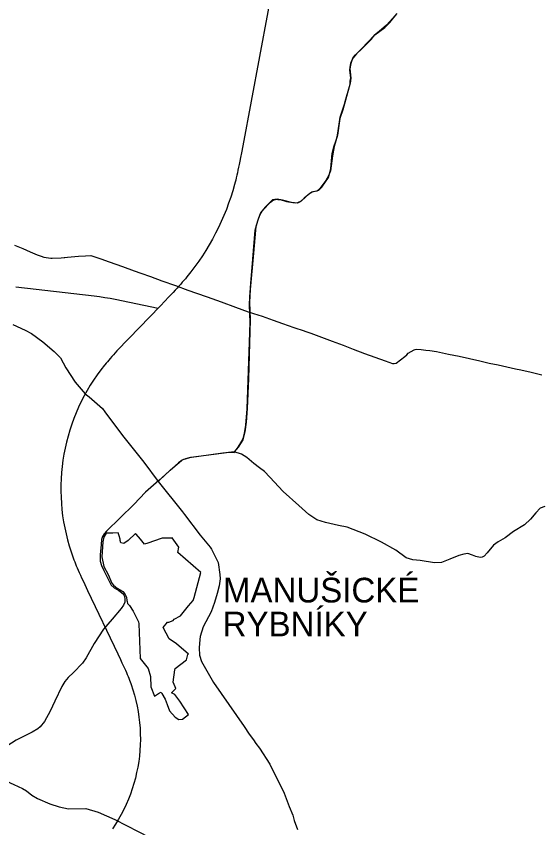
# Model space of a CAD drawing. Extents: x -789162 to -606354, y -1062736 to -945481.
# Drawn here: x -727625 to -725497, y -975863 to -972579 of the extents above; entities that cross this region are included whole.
import ezdxf

# ---------------------------------------------------------------- set-up
doc = ezdxf.new("R2010")
doc.units = 0
for name, color, linetype in [('_SIRSI VZTAHY_CYKLOTRASY MISTNI S', 7, 'Continuous'), ('_SIRSI VZTAHY_NATURA_EVL', 7, 'Continuous'), ('_SIRSI VZTAHY_NATURA_EVL_POPIS_KOD', 7, 'Continuous'), ('_SIRSI VZTAHY_SILNICE I TRIDY_NAVRH', 7, 'Continuous'), ('_SIRSI VZTAHY_SILNICE III TRIDY_STAV', 7, 'Continuous'), ('_SIRSI VZTAHY_VTL PLYNOVOD', 7, 'Continuous')]:
    doc.layers.add(name, color=color, linetype=linetype)

msp = doc.modelspace()

# ---------------------------------------------------------------- linework, layer by layer
at = {"layer": '_SIRSI VZTAHY_CYKLOTRASY MISTNI S'}
for points in [[(-727050.7, -974462), (-727044.1, -974456.3), (-727001.4, -974416), (-726991.4, -974406.6), (-726955.1, -974376.9), (-726945.6, -974371.9), (-726939.4, -974369.8), (-726917.6, -974363.2), (-726762.7, -974343.4), (-726742.3, -974343.9), (-726725.9, -974322.6), (-726711.9, -974299.1), (-726704.6, -974283.7), (-726700.1, -974266.1), (-726694.7, -974233.5), (-726690.3, -974167.8), (-726680, -973898.4), (-726678.4, -973818.6), (-726680.3, -973747.8), (-726679.3, -973714.4), (-726673.9, -973643.2), (-726666.5, -973562.6), (-726657.3, -973444.5), (-726646.5, -973407.4), (-726638.2, -973384.2), (-726627.7, -973365.1), (-726595.9, -973332), (-726590.3, -973327.8), (-726580.4, -973322.1), (-726570.4, -973319.8), (-726565.4, -973320.3), (-726556.6, -973321.1), (-726530.5, -973328.6), (-726505.5, -973333.1), (-726492.5, -973334.3), (-726484.5, -973332.6), (-726469.9, -973325.5), (-726436.3, -973295.2), (-726428, -973289.7), (-726407.4, -973285.6), (-726400.1, -973283), (-726394, -973277.6), (-726388, -973270.4), (-726373.1, -973249.1), (-726360.3, -973231), (-726352.1, -973202.4), (-726350.6, -973194.9), (-726345.2, -973134.6), (-726338.7, -973107.2), (-726329.3, -973080), (-726325.6, -973066.9), (-726322.6, -973051.6), (-726313.5, -972987.2), (-726296, -972934.5), (-726293.1, -972924.1), (-726273.4, -972854), (-726272.6, -972841.7), (-726270.4, -972828.1), (-726273.9, -972796.7), (-726273.4, -972785.2), (-726270.9, -972768.7), (-726260.4, -972746.3), (-726251, -972734.8), (-726222.2, -972706.6), (-726188.3, -972672.7), (-726173, -972654.2), (-726132.7, -972625.3), (-726112.6, -972604.4), (-726083.5, -972569.9)], [(-727638.7, -973826.1), (-727588, -973849.2), (-727563.1, -973862.9), (-727516.9, -973896.4), (-727471.8, -973936), (-727445.9, -973960.8), (-727423.7, -974001.7), (-727385.7, -974059.7), (-727345.7, -974106.7), (-727329.2, -974119.2), (-727308.2, -974138.8), (-727275.2, -974166.8), (-727266.6, -974179.8), (-727194.1, -974275.1), (-727108.3, -974383.8), (-727050.7, -974462), (-726952.1, -974584.7), (-726943.6, -974595.8), (-726880.1, -974678.4), (-726840.3, -974727.8), (-726834.6, -974735.5), (-726807.6, -974789.4), (-726800.3, -974838.6), (-726799.3, -974855.3), (-726803.7, -974884.1), (-726811.5, -974915.5), (-726822.8, -974951), (-726836, -974988.7), (-726867.9, -975049.7), (-726880.1, -975089.4), (-726881.2, -975100.9), (-726884, -975135.4), (-726882.6, -975164.3), (-726874.2, -975190), (-726825.8, -975275.2), (-726701.4, -975452.8), (-726681.3, -975484.1), (-726664.4, -975507.6), (-726654.4, -975521.5), (-726640.6, -975540.7), (-726598.5, -975605.1), (-726539.7, -975722.9), (-726519.7, -975776.5), (-726505, -975812.5), (-726500.1, -975833.5), (-726486.8, -975870.3)]]:
    msp.add_lwpolyline(points, dxfattribs=at)
at = {"layer": '_SIRSI VZTAHY_NATURA_EVL'}
msp.add_lwpolyline([(-727176.9, -974942.9), (-727176, -974947.4), (-727174.4, -974956), (-727166.6, -974963.8), (-727151.8, -974987.1), (-727130.4, -975029.8), (-727128.4, -975038.1), (-727123.4, -975177.6), (-727090.6, -975219), (-727081.7, -975251.2), (-727080.4, -975292.6), (-727065.4, -975331.1), (-727044.2, -975316.9), (-727038, -975314.6), (-727035.2, -975319.7), (-727022.5, -975342.6), (-727014.4, -975364.9), (-727004.9, -975390), (-726981.4, -975415.1), (-726966.4, -975425), (-726951.1, -975423.6), (-726927.6, -975405.3), (-726962.8, -975351.1), (-726982.3, -975324.2), (-726995.6, -975316.5), (-726978.3, -975300.2), (-726981.4, -975292.7), (-726989.2, -975274.2), (-726982.3, -975224.1), (-726981.6, -975218.7), (-726935.6, -975183.4), (-726930.3, -975161.3), (-726927.3, -975160), (-726976.6, -975119.1), (-727005.1, -975098), (-727030.2, -975052.8), (-727012.3, -975030.7), (-727006.9, -975030.6), (-726989.5, -975024.4), (-726985.1, -975019.2), (-726959.2, -975005.4), (-726926.8, -974964.6), (-726908.8, -974943.8), (-726904.4, -974931.6), (-726877, -974829.5), (-726970.3, -974749.1), (-726965.9, -974728.2), (-726993, -974690.5), (-726997.8, -974690.6), (-727033.6, -974691.6), (-727037.4, -974692.8), (-727065.2, -974702.1), (-727091.5, -974711), (-727105.2, -974715.5), (-727121.9, -974695.1), (-727139.1, -974674.9), (-727142.4, -974672), (-727171.9, -974700.8), (-727189.6, -974712.1), (-727200.9, -974710.4), (-727203.8, -974700.9), (-727204.6, -974694.8), (-727208.6, -974681.4), (-727212.2, -974669.6), (-727233.2, -974670.5), (-727261, -974671.5), (-727268.2, -974683.9), (-727271.6, -974691.9), (-727274, -974706.6), (-727277.9, -974766.2), (-727269.8, -974805.2), (-727252.8, -974838.1), (-727237.7, -974873), (-727231.2, -974881.7), (-727223.1, -974888.4), (-727216.5, -974893.2), (-727204, -974899.8), (-727193.4, -974907.3), (-727184.6, -974916.6), (-727179, -974930.3)], close=True, dxfattribs=at)
at = {"layer": '_SIRSI VZTAHY_SILNICE I TRIDY_NAVRH'}
for points in [[(-726471.8, -971837.2), (-726707.6, -973103.3), (-726713, -973132.3), (-726716.4, -973150.2), (-726719.3, -973165.1), (-726722, -973178.4), (-726724.5, -973190.5), (-726727, -973201.9), (-726729.4, -973212.6), (-726731.7, -973222.8), (-726734.1, -973232.6), (-726736.4, -973242), (-726738.7, -973251.1), (-726741, -973259.7), (-726748.3, -973285.2), (-726756.2, -973310.6), (-726764.8, -973335.7), (-726774.1, -973360.5), (-726784, -973385.1), (-726794.6, -973409.5), (-726805.8, -973433.5), (-726817.7, -973457.3), (-726830.2, -973480.7), (-726843.3, -973503.8), (-726857, -973526.5), (-726871.3, -973548.8), (-726886.2, -973570.8), (-726901.7, -973592.4), (-726917.7, -973613.5), (-726934.3, -973634.2), (-726940, -973641.1), (-726946.1, -973648.2), (-726952.4, -973655.6), (-726959, -973663.1), (-726965.9, -973671), (-726973.3, -973679.1), (-726981.1, -973687.7), (-726989.6, -973696.8), (-726998.9, -973706.7), (-727009.3, -973717.8), (-727021.9, -973730.9), (-727042.4, -973752.1), (-727169.5, -973883.5), (-727187.9, -973902.6), (-727199.2, -973914.4), (-727208.6, -973924.3), (-727216.9, -973933.2), (-727224.5, -973941.5), (-727231.5, -973949.2), (-727238.1, -973956.5), (-727244.3, -973963.6), (-727250.2, -973970.4), (-727255.8, -973977.1), (-727261.2, -973983.5), (-727266.4, -973989.8), (-727267.1, -973990.7), (-727282.5, -974010.5), (-727297.3, -974030.7), (-727311.4, -974051.3), (-727324.9, -974072.4), (-727337.7, -974093.9), (-727349.8, -974115.8), (-727361.2, -974138), (-727372, -974160.7), (-727382, -974183.6), (-727391.3, -974206.8), (-727399.9, -974230.3), (-727407.7, -974254.1), (-727414.8, -974278.1), (-727421.1, -974302.3), (-727426.7, -974326.7), (-727431.5, -974351.3), (-727435.5, -974376), (-727438.8, -974400.8), (-727441.3, -974425.7), (-727443, -974450.6), (-727443.9, -974475.6), (-727444.1, -974500.7), (-727443.4, -974525.7), (-727442, -974550.7), (-727439.8, -974575.6), (-727436.8, -974600.4), (-727433, -974625.2), (-727428.5, -974649.8), (-727423.2, -974674.2), (-727417.1, -974698.5), (-727410.3, -974722.6), (-727402.7, -974746.4), (-727394.4, -974770.1), (-727394, -974771.1), (-727391.2, -974778.8), (-727388.1, -974786.6), (-727384.9, -974794.7), (-727381.5, -974803), (-727377.8, -974811.7), (-727373.9, -974820.8), (-727369.7, -974830.3), (-727365.2, -974840.5), (-727360.1, -974851.6), (-727354.4, -974864), (-727347.4, -974878.8), (-727336, -974902.7), (-727213.5, -975159.9), (-727203.1, -975181.7), (-727196.8, -975195.2), (-727191.5, -975206.5), (-727187, -975216.6), (-727182.8, -975225.9), (-727179, -975234.6), (-727175.5, -975242.9), (-727172.2, -975250.8), (-727169.2, -975258.4), (-727166.3, -975265.8), (-727163.5, -975272.9), (-727161, -975279.9), (-727159.7, -975283.6), (-727152.5, -975305), (-727146, -975326.7), (-727140.4, -975348.6), (-727135.4, -975370.6), (-727131.3, -975392.9), (-727127.9, -975415.2), (-727125.3, -975437.7), (-727123.5, -975460.2), (-727122.5, -975482.8), (-727122.3, -975505.4), (-727122.8, -975527.9), (-727124.1, -975550.5), (-727126.2, -975573), (-727129.1, -975595.4), (-727132.8, -975617.7), (-727137.3, -975639.9), (-727142.5, -975661.9), (-727148.4, -975683.7), (-727155.2, -975705.2), (-727162.6, -975726.6), (-727170.9, -975747.6), (-727179.8, -975768.4), (-727189.5, -975788.8), (-727199.8, -975808.9), (-727210.9, -975828.6), (-727222.6, -975847.9), (-727235, -975866.8)], [(-727626.1, -973674), (-727309.9, -973710.7), (-727288.2, -973713.4), (-727266.6, -973716.7), (-727245.1, -973720.4), (-727223.6, -973724.5), (-727050.2, -973760.2)]]:
    msp.add_lwpolyline(points, dxfattribs=at)
at = {"layer": '_SIRSI VZTAHY_SILNICE III TRIDY_STAV'}
for points in [[(-726083.8, -972567.7), (-726099.9, -972587), (-726125.4, -972615.6), (-726154.1, -972639.5), (-726175.3, -972657), (-726227.6, -972711.5), (-726247.9, -972730.9), (-726260.7, -972747.2), (-726266.3, -972758.5), (-726270.8, -972770.9), (-726274.3, -972791.6), (-726273.1, -972804.7), (-726269.8, -972830), (-726272.4, -972849.3), (-726291.6, -972918.8), (-726302.7, -972957.9), (-726314.4, -972993.1), (-726323.8, -973060.8), (-726337.1, -973106.5), (-726345.1, -973144), (-726352.7, -973204.3), (-726360.6, -973225.1), (-726371.8, -973244.2), (-726395.1, -973276.1), (-726408, -973286.5), (-726424.5, -973289.1), (-726436.8, -973297), (-726459.7, -973315.7), (-726475.8, -973329.7), (-726486.4, -973335), (-726510.9, -973332.9), (-726547.5, -973323.9), (-726568.3, -973318.9), (-726586.7, -973322.7), (-726601.9, -973336.4), (-726616.4, -973351.9), (-726636.2, -973374.8), (-726645.7, -973399.8), (-726654.2, -973430.1), (-726658.8, -973475.8), (-726664.8, -973537.7), (-726677.6, -973684.9), (-726681, -973736.4), (-726678.1, -973807), (-726684.5, -974045.4), (-726689.8, -974165.9), (-726694.6, -974221.7), (-726698.8, -974260.9), (-726707.8, -974292.8), (-726726.9, -974323.6), (-726742.8, -974341.5)], [(-726742.8, -974341.5), (-726788.7, -974347.3), (-726925.2, -974366.5), (-726939.8, -974370.3), (-726953.2, -974376.2), (-726967.8, -974386.6), (-727047.1, -974458.1), (-727100.8, -974504.4), (-727148, -974555.6), (-727259.5, -974663.4), (-727268.7, -974673.7), (-727275.4, -974684.6), (-727279.5, -974697.2), (-727281.4, -974716.8), (-727284.4, -974758.8), (-727284.3, -974784.8), (-727279.5, -974801.9), (-727269.9, -974822.1), (-727249.9, -974862.5), (-727239.9, -974881.3), (-727228.4, -974892.4), (-727209.4, -974903.2), (-727191.6, -974916.2), (-727186.2, -974925.4), (-727184.6, -974937.5), (-727185.6, -974950.8), (-727190, -974962), (-727200.5, -974975.9), (-727236.6, -975018.6), (-727271.7, -975059.4), (-727309.9, -975117.8), (-727341.1, -975175.6), (-727357, -975196.6), (-727393.2, -975235.2), (-727414.6, -975255.3), (-727428.4, -975271.2), (-727440.8, -975291.5), (-727468.8, -975350.6), (-727486.9, -975390.9), (-727510, -975433.2), (-727527.8, -975455), (-727537.7, -975463.2), (-727560, -975475.7), (-727624.7, -975509.1), (-727662.9, -975532.5)], [(-725485.5, -974563.5), (-725504.2, -974569.9), (-725521.8, -974588), (-725543, -974614), (-725567.9, -974636.8), (-725611.7, -974663.8), (-725645.5, -974689.9), (-725673.3, -974706.1), (-725692.4, -974719.1), (-725718.7, -974751.1), (-725730.5, -974763.8), (-725738.7, -974768), (-725746.9, -974769), (-725764.1, -974764.8), (-725777.4, -974759.7), (-725796.2, -974753.7), (-725813, -974755.3), (-725833.3, -974761.3), (-725869.5, -974776.7), (-725903.1, -974789.4), (-725932.2, -974791.3), (-725989.4, -974782.1), (-726018.7, -974779.1), (-726045.7, -974771.2), (-726088.2, -974740.4), (-726146.6, -974708), (-726212.5, -974674.6), (-726285.3, -974647.3), (-726319.6, -974640), (-726373.3, -974627.8), (-726407.9, -974616.7), (-726439.7, -974595.4), (-726481.2, -974558.6), (-726543.6, -974502.5), (-726597.6, -974443.8), (-726619.1, -974421.3), (-726640.2, -974406.7), (-726662.4, -974388.7), (-726690.9, -974364.7), (-726712.8, -974351.4), (-726742.8, -974341.5)], [(-727736.5, -975637.4), (-727712.1, -975653.2), (-727634.3, -975688.6), (-727599.9, -975703.8), (-727582.8, -975713.9), (-727562.1, -975731.6), (-727538.7, -975744.3), (-727488.3, -975765.6), (-727451.1, -975778.8), (-727412.6, -975786.6), (-727343.3, -975785.2), (-727293.4, -975800.6), (-727226, -975829.8), (-727084.3, -975902.6)]]:
    msp.add_lwpolyline(points, dxfattribs=at)
at = {"layer": '_SIRSI VZTAHY_VTL PLYNOVOD'}
msp.add_lwpolyline([(-727631.1, -973505.4), (-727598.6, -973519.1), (-727567.7, -973532.3), (-727539.4, -973544.1), (-727539.4, -973544.1), (-727523.6, -973550.4), (-727512.6, -973554), (-727485, -973558.5), (-727478.6, -973558.4), (-727443.3, -973556.1), (-727430.4, -973554.9), (-727430.1, -973554.9), (-727429, -973554.9), (-727428.6, -973554.8), (-727417.2, -973553.9), (-727372.5, -973549.6), (-727343.8, -973548.1), (-727323.2, -973547.9), (-727310.3, -973551.8), (-727282.6, -973561.2), (-727248.3, -973573.5), (-727193.9, -973592.4), (-727146.8, -973608.9), (-727119.9, -973618.5), (-727119.8, -973618.5), (-727119.8, -973618.5), (-727081.1, -973632.2), (-727035.1, -973649.2), (-726980.5, -973668.7), (-726929.8, -973687.1), (-726895.5, -973699.5), (-726851.3, -973715.1), (-726794.6, -973734.9), (-726736.7, -973756.6), (-726685.2, -973774.8), (-726672.6, -973778.7), (-726664.2, -973781.4), (-726629.7, -973793.2), (-726585.3, -973809), (-726546.9, -973822.6), (-726501, -973838.1), (-726458.5, -973852.5), (-726455.8, -973853.4), (-726432.3, -973861.8), (-726389.4, -973878.1), (-726346.2, -973894.2), (-726301.9, -973910.3), (-726261.4, -973925.8), (-726215.2, -973943.4), (-726172.9, -973958.4), (-726131, -973973.6), (-726102.1, -973984.2), (-726094.4, -973984.9), (-726086.8, -973982.8), (-726052.2, -973956.7), (-726044.1, -973949.5), (-726037.5, -973943.2), (-726014.4, -973928.5), (-726009.8, -973927.3), (-726002.7, -973926.1), (-725985.9, -973927.9), (-725967.2, -973929.9), (-725950.1, -973932), (-725922.9, -973935.9), (-725874.9, -973946.2), (-725831.4, -973955.3), (-725790.4, -973964.1), (-725748.6, -973973.9), (-725709.7, -973982.4), (-725674, -973989.9), (-725638.7, -973997.8), (-725603.4, -974005.7), (-725581.7, -974010.6), (-725540.2, -974020.1), (-725496.5, -974030.6)], dxfattribs=at)

# ---------------------------------------------------------------- texts
at = {"layer": '_SIRSI VZTAHY_NATURA_EVL_POPIS_KOD'}
for s, p in [('MANUŠICKÉ', (-726787.9, -974951.4)), ('RYBNÍKY', (-726789, -975088.6))]:
    msp.add_text(s, height=100, dxfattribs=at).set_placement(p)

doc.saveas('drawing.dxf')
